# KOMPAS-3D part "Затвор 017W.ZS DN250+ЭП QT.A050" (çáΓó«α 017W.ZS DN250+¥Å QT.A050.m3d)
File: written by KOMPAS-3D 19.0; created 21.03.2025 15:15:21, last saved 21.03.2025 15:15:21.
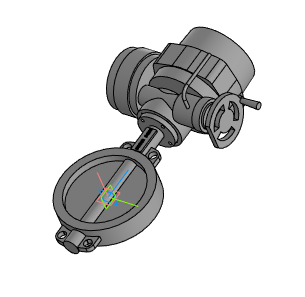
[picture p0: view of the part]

Document properties: Полное имя файла: Затвор 017W.ZS DN250+ЭП QT.A050.a3d

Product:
- Part/product: Затвор 017W.ZS DN250+ЭП QT.A050
    Масса: 139.627

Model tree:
1. Операция без истории:1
